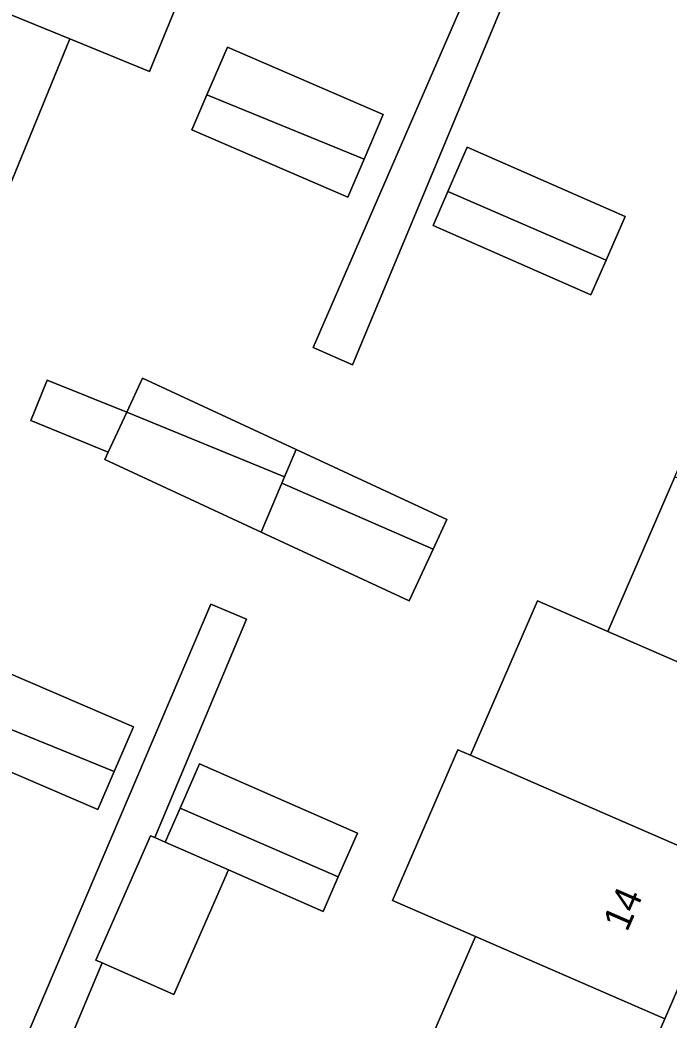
# Model space of a CAD drawing. Extents: x 162803 to 163818, y 381639 to 382475.
# Drawn here: x 163303.35 to 163327.14, y 382031.48 to 382068.11 of the extents above; entities that cross this region are included whole.
import ezdxf

# ---------------------------------------------------------------- set-up
doc = ezdxf.new("R2010")
doc.units = 0
for name, color, linetype in [('IMGEO_Erf', 7, 'Continuous'), ('IMGEO_Pand', 7, 'Continuous'), ('IMGEO_Pand_nummerreeks', 7, 'Continuous'), ('IMGEO_Voetpad_open', 7, 'Continuous')]:
    doc.layers.add(name, color=color, linetype=linetype)

msp = doc.modelspace()

# ---------------------------------------------------------------- linework, layer by layer
at = {"layer": 'IMGEO_Erf'}
for points in [[(163302.149, 382089.42), (163278.323, 382030.765), (163280.108, 382030.045), (163299.767, 382021.917), (163310.343, 382046.709), (163311.654, 382046.166), (163308.291, 382038.159), (163308.674, 382037.991), (163309.22, 382039.238), (163309.929, 382040.858), (163315.717, 382038.323), (163315.015, 382036.72), (163314.462, 382035.456), (163310.991, 382036.976), (163308.992, 382032.413), (163306.362, 382033.566), (163300.278, 382019.082), (163300.993, 382018.779), (163312.389, 382016.368), (163320.918, 382012.914), (163322.712, 382012.16), (163347.746, 382069.96)], [(163326.145, 382080.906), (163315.541, 382055.478), (163314.095, 382056.11), (163324.491, 382080.044)], [(163310.414, 382071.903), (163308.095, 382066.225), (163305.176, 382067.417), (163302.957, 382061.984), (163300.651, 382056.339), (163298.355, 382050.716), (163296.013, 382044.982), (163293.757, 382039.459), (163291.465, 382033.847), (163288.936, 382027.656), (163286.453, 382028.671), (163281.823, 382030.561), (163284.352, 382036.752), (163286.644, 382042.364), (163288.9, 382047.887), (163291.241, 382053.62), (163293.538, 382059.244), (163295.844, 382064.889), (163298.063, 382070.322)], [(163344.303, 382071.395), (163341.691, 382065.383), (163339.343, 382059.978), (163336.796, 382054.114), (163334.295, 382048.358), (163331.836, 382042.699), (163329.38, 382037.044), (163326.981, 382031.522), (163324.508, 382025.829)], [(163317.567, 382028.844), (163320.041, 382034.537), (163317.002, 382035.857), (163319.401, 382041.379), (163319.864, 382041.178), (163322.321, 382046.833), (163324.896, 382045.714), (163327.355, 382051.374), (163329.856, 382057.13), (163332.403, 382062.994), (163334.751, 382068.399)]]:
    msp.add_lwpolyline(points, dxfattribs=at)
for points in [[(163309.652, 382064.084), (163310.203, 382065.364), (163310.955, 382067.111), (163316.668, 382064.652), (163315.962, 382063.012), (163315.365, 382061.625)], [(163319.744, 382063.45), (163325.532, 382060.915), (163324.831, 382059.314), (163324.277, 382058.048), (163318.489, 382060.583), (163319.036, 382061.832)], [(163313.47, 382052.377), (163319.002, 382049.807), (163318.501, 382048.727), (163317.619, 382046.83), (163312.19, 382049.351), (163306.459, 382052.013), (163306.585, 382052.284), (163303.742, 382053.444), (163304.341, 382054.912), (163307.262, 382053.74), (163307.842, 382054.99)], [(163307.505, 382042.217), (163306.799, 382040.577), (163306.202, 382039.19), (163300.489, 382041.649), (163301.04, 382042.929), (163301.792, 382044.676)]]:
    msp.add_lwpolyline(points, close=True, dxfattribs=at)
at = {"layer": 'IMGEO_Pand'}
for points in [[(163310.414, 382071.903), (163307.495, 382073.095), (163300.382, 382076), (163298.063, 382070.322), (163305.176, 382067.417), (163308.095, 382066.225)], [(163302.957, 382061.984), (163305.176, 382067.417), (163298.063, 382070.322), (163295.844, 382064.889)], [(163310.203, 382065.364), (163315.962, 382063.012), (163316.668, 382064.652), (163310.955, 382067.111)], [(163310.203, 382065.364), (163309.652, 382064.084), (163315.365, 382061.625), (163315.962, 382063.012)], [(163319.036, 382061.832), (163324.831, 382059.314), (163325.532, 382060.915), (163319.744, 382063.45)], [(163319.036, 382061.832), (163318.489, 382060.583), (163324.277, 382058.048), (163324.831, 382059.314)], [(163307.262, 382053.74), (163304.341, 382054.912), (163303.742, 382053.444), (163306.585, 382052.284)], [(163313.047, 382051.377), (163313.47, 382052.377), (163307.842, 382054.99), (163307.262, 382053.74)], [(163307.262, 382053.74), (163306.585, 382052.284), (163306.459, 382052.013), (163312.19, 382049.351), (163312.947, 382051.14), (163313.047, 382051.377)], [(163318.501, 382048.727), (163319.002, 382049.807), (163313.47, 382052.377), (163313.047, 382051.377), (163312.947, 382051.14)], [(163318.501, 382048.727), (163312.947, 382051.14), (163312.19, 382049.351), (163317.619, 382046.83)], [(163331.836, 382042.699), (163334.295, 382048.358), (163327.355, 382051.374), (163324.896, 382045.714)], [(163331.836, 382042.699), (163324.896, 382045.714), (163322.321, 382046.833), (163319.864, 382041.178), (163322.44, 382040.059), (163329.38, 382037.044)], [(163301.04, 382042.929), (163306.799, 382040.577), (163307.505, 382042.217), (163301.792, 382044.676)], [(163301.04, 382042.929), (163300.489, 382041.649), (163306.202, 382039.19), (163306.799, 382040.577)], [(163329.38, 382037.044), (163322.44, 382040.059), (163319.864, 382041.178), (163319.401, 382041.379), (163317.002, 382035.857), (163320.041, 382034.537), (163326.981, 382031.522)], [(163309.22, 382039.238), (163315.015, 382036.72), (163315.717, 382038.323), (163309.929, 382040.858)], [(163309.22, 382039.238), (163308.674, 382037.991), (163310.991, 382036.976), (163314.462, 382035.456), (163315.015, 382036.72)], [(163310.991, 382036.976), (163308.674, 382037.991), (163308.291, 382038.159), (163308.133, 382038.228), (163306.135, 382033.665), (163306.362, 382033.566), (163308.992, 382032.413)], [(163320.041, 382034.537), (163317.567, 382028.844), (163324.508, 382025.829), (163326.981, 382031.522)]]:
    msp.add_lwpolyline(points, close=True, dxfattribs=at)
at = {"layer": 'IMGEO_Voetpad_open'}
for points in [[(163308.836, 382088.261), (163308.265, 382086.902), (163309.954, 382086.213), (163312.438, 382085.197), (163315.027, 382084.14), (163324.491, 382080.044), (163314.095, 382056.11), (163315.541, 382055.478), (163326.145, 382080.906), (163325.963, 382080.979), (163324.491, 382081.57), (163324.52, 382081.642)], [(163311.654, 382046.166), (163310.343, 382046.709), (163299.767, 382021.917), (163280.108, 382030.045), (163279.555, 382028.679), (163296.851, 382021.352), (163292.667, 382011.896), (163294.314, 382011.231), (163295.617, 382014.312), (163298.036, 382020.03), (163299.517, 382019.404), (163300.278, 382019.082), (163306.362, 382033.566), (163306.135, 382033.665), (163308.133, 382038.228), (163308.291, 382038.159)]]:
    msp.add_lwpolyline(points, close=True, dxfattribs=at)

# ---------------------------------------------------------------- texts
at = {"layer": 'IMGEO_Pand_nummerreeks'}
msp.add_text('14', height=1, rotation=66.5204, dxfattribs=at).set_placement((163325.603, 382034.674))

doc.saveas('drawing.dxf')
